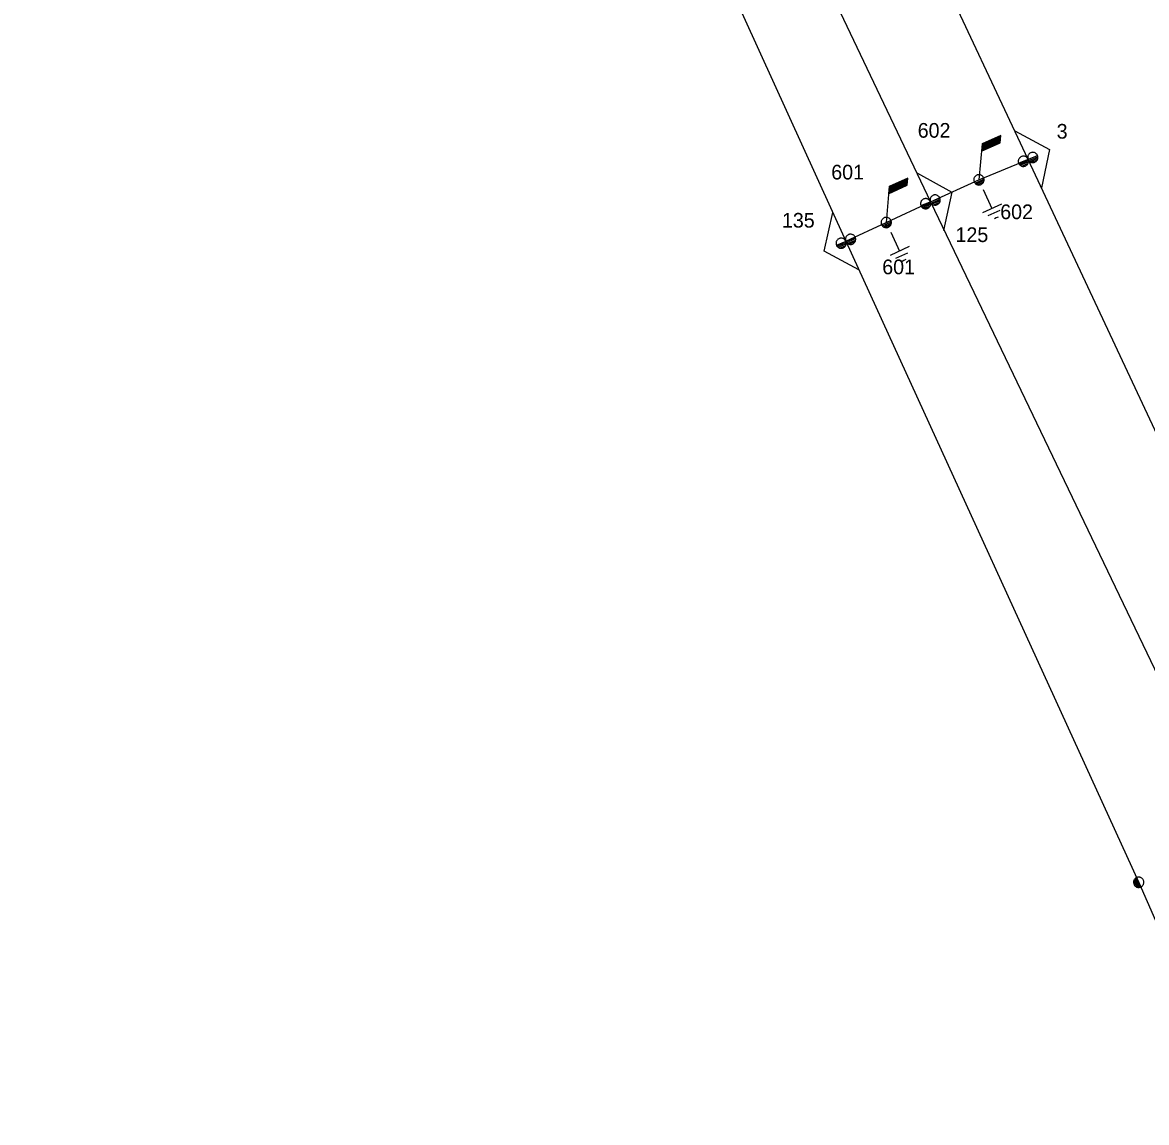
# Model space of a CAD drawing. Extents: x -536397 to -535454, y -1201642 to -1200953.
# Drawn here: x -536387.9 to -536253.8, y -1201275.2 to -1201144 of the extents above; entities that cross this region are included whole.
import ezdxf

# ---------------------------------------------------------------- set-up
doc = ezdxf.new("R2010")
doc.units = 0
for name, color, linetype in [('DOPLŇ_POPISY', 7, 'Continuous'), ('ELE_EON', 7, 'Continuous'), ('ELE_EON_POPIS', 7, 'Continuous'), ('Implicitní', 7, 'Continuous'), ('KN_HRAN_POHYBLIVÁ', 7, 'Continuous'), ('KONEC_VEDENÍ', 7, 'Continuous'), ('PLG_EXPORT_GPE', 7, 'Continuous'), ('PODZEM_NN_POPIS', 7, 'Continuous'), ('RÁMEČEK', 7, 'Continuous'), ('TECH_OCHR_PÁSMO_HRAN', 7, 'Continuous')]:
    doc.layers.add(name, color=color, linetype=linetype)

# ---------------------------------------------------------------- blocks, each defined once
blk = doc.blocks.new('VN860')
at = {"layer": 'RÁMEČEK'}
for points in [[(-3.74, 0), (0.01, 2.82)], [(0.01, 2.82), (3.76, 0)]]:
    blk.add_lwpolyline(points, dxfattribs=at)
blk = doc.blocks.new('VN440')
at = {"layer": 'ELE_EON_POPIS'}
for points in [[(1.22, 0), (1.21, 0.13), (1.19, 0.25), (1.16, 0.38), (1.11, 0.5), (1.05, 0.61), (0.98, 0.72), (0.9, 0.82), (0.81, 0.91), (0.71, 0.99), (0.6, 1.06), (0.49, 1.12), (0.37, 1.16), (0.25, 1.2), (0.12, 1.22), (-0.01, 1.22), (-0.14, 1.22), (-0.26, 1.2), (-0.39, 1.16), (-0.51, 1.12), (-0.62, 1.06), (-0.73, 0.99), (-0.83, 0.91), (-0.92, 0.82), (-1, 0.72), (-1.07, 0.61), (-1.13, 0.5), (-1.18, 0.38), (-1.21, 0.25), (-1.23, 0.13), (-1.24, 0), (-1.23, -0.13), (-1.21, -0.26), (-1.18, -0.38), (-1.13, -0.5), (-1.07, -0.62), (-1, -0.73), (-0.92, -0.83), (-0.83, -0.92), (-0.73, -1), (-0.62, -1.07), (-0.51, -1.13), (-0.39, -1.17), (-0.26, -1.2), (-0.14, -1.23), (-0.01, -1.23), (0.12, -1.23), (0.25, -1.2), (0.37, -1.17), (0.49, -1.13), (0.6, -1.07), (0.71, -1), (0.81, -0.92), (0.9, -0.83), (0.98, -0.73), (1.05, -0.62), (1.11, -0.5), (1.16, -0.38), (1.19, -0.26), (1.21, -0.13), (1.22, 0)], [(-1.24, 0), (1.22, 0)], [(-1.18, -0.34), (1.1, -0.34)], [(-1.01, -0.63), (0.97, -0.63)], [(-0.74, -0.92), (0.68, -0.92)]]:
    blk.add_lwpolyline(points, dxfattribs=at)
blk = doc.blocks.new('VN810')
at = {"layer": 'PLG_EXPORT_GPE'}
for points in [[(0, -1.25), (0, -3.75)], [(1.25, -3.75), (-1.25, -3.75)], [(0.77, -4.37), (-0.8, -4.37)], [(0, -5), (-0.25, -5)], [(0.27, -5), (0, -5)]]:
    blk.add_lwpolyline(points, dxfattribs=at)
blk = doc.blocks.new('VN450')
at = {"layer": 'ELE_EON_POPIS'}
for points in [[(0, 0), (-0.01, 0.13), (-0.03, 0.25), (-0.06, 0.38), (-0.11, 0.5), (-0.16, 0.61), (-0.23, 0.72), (-0.31, 0.82), (-0.4, 0.91), (-0.5, 0.99), (-0.61, 1.06), (-0.72, 1.11), (-0.84, 1.16), (-0.97, 1.19), (-1.09, 1.21), (-1.22, 1.22), (-1.35, 1.21), (-1.47, 1.19), (-1.59, 1.16), (-1.71, 1.11), (-1.83, 1.06), (-1.93, 0.99), (-2.03, 0.91), (-2.12, 0.82), (-2.2, 0.72), (-2.27, 0.61), (-2.33, 0.5), (-2.38, 0.38), (-2.41, 0.25), (-2.43, 0.13), (-2.44, 0), (-2.43, -0.13), (-2.41, -0.25), (-2.38, -0.38), (-2.33, -0.5), (-2.27, -0.61), (-2.2, -0.72), (-2.12, -0.82), (-2.03, -0.91), (-1.93, -0.99), (-1.83, -1.06), (-1.71, -1.11), (-1.59, -1.16), (-1.47, -1.19), (-1.35, -1.21), (-1.22, -1.22), (-1.09, -1.21), (-0.97, -1.19), (-0.84, -1.16), (-0.72, -1.11), (-0.61, -1.06), (-0.5, -0.99), (-0.4, -0.91), (-0.31, -0.82), (-0.23, -0.72), (-0.16, -0.61), (-0.11, -0.5), (-0.06, -0.38), (-0.03, -0.25), (-0.01, -0.13), (0, 0)], [(-2.44, 0), (2.44, 0)], [(2.44, 0), (2.43, 0.13), (2.41, 0.25), (2.38, 0.38), (2.33, 0.5), (2.27, 0.61), (2.2, 0.72), (2.12, 0.82), (2.03, 0.91), (1.94, 0.99), (1.83, 1.06), (1.71, 1.11), (1.6, 1.16), (1.47, 1.19), (1.35, 1.21), (1.22, 1.22), (1.09, 1.21), (0.97, 1.19), (0.84, 1.16), (0.72, 1.11), (0.61, 1.06), (0.5, 0.99), (0.4, 0.91), (0.31, 0.82), (0.23, 0.72), (0.16, 0.61), (0.11, 0.5), (0.06, 0.38), (0.03, 0.25), (0.01, 0.13), (0, 0), (0.01, -0.13), (0.03, -0.25), (0.06, -0.38), (0.11, -0.5), (0.16, -0.61), (0.23, -0.72), (0.31, -0.82), (0.4, -0.91), (0.5, -0.99), (0.61, -1.06), (0.72, -1.11), (0.84, -1.16), (0.97, -1.19), (1.09, -1.21), (1.22, -1.22), (1.35, -1.21), (1.47, -1.19), (1.6, -1.16), (1.71, -1.11), (1.83, -1.06), (1.94, -0.99), (2.03, -0.91), (2.12, -0.82), (2.2, -0.72), (2.27, -0.61), (2.33, -0.5), (2.38, -0.38), (2.41, -0.25), (2.43, -0.13), (2.44, 0)], [(-2.4, -0.31), (-0.04, -0.31)], [(-2.26, -0.61), (-0.17, -0.61)], [(-2.01, -0.92), (-0.42, -0.92)], [(0.04, -0.31), (2.4, -0.31)], [(0.17, -0.61), (2.27, -0.61)], [(0.42, -0.92), (2.02, -0.92)]]:
    blk.add_lwpolyline(points, dxfattribs=at)
blk = doc.blocks.new('VN001')
at = {"layer": 'Implicitní'}
for p, q in [((1.73, 3.03), (4.14, 3.03)), ((1.76, 3.08), (4.17, 3.08)), ((1.79, 3.13), (4.2, 3.13)), ((1.82, 3.18), (4.23, 3.18)), ((1.85, 3.23), (4.26, 3.23)), ((1.87, 3.28), (4.29, 3.28)), ((1.9, 3.33), (4.32, 3.33)), ((1.93, 3.38), (4.35, 3.38)), ((1.96, 3.43), (4.37, 3.43)), ((1.99, 3.48), (4.4, 3.48)), ((2.02, 3.53), (4.43, 3.53)), ((2.05, 3.58), (4.46, 3.58)), ((2.07, 3.63), (4.49, 3.63)), ((2.1, 3.68), (4.52, 3.68)), ((2.13, 3.73), (2.54, 3.73))]:
    blk.add_line(p, q, dxfattribs=at)
blk.add_lwpolyline([(2.13, 3.73), (0, 0)], dxfattribs=at)
blk.add_lwpolyline([(4.55, 3.73), (2.13, 3.73), (1.7, 2.98), (4.12, 2.99)], close=True, dxfattribs=at)

msp = doc.modelspace()

# ---------------------------------------------------------------- linework, layer by layer
at = {"layer": 'ELE_EON'}
for points in [[(-536387.85, -1200953.47), (-536384.37, -1200962.05), (-536350.06, -1201037.34), (-536318.97, -1201105.71), (-536289.66, -1201170.08)], [(-536346.44, -1200953.53), (-536361.66, -1200993.24), (-536320.28, -1201079.87), (-536279.58, -1201165.38)], [(-536267.93, -1201160.31), (-536301.44, -1201088.98), (-536346, -1200993.45), (-536331, -1200953.56)], [(-536219.44, -1201264.18), (-536230.28, -1201240.65), (-536267.93, -1201160.31)], [(-536279.58, -1201165.38), (-536243.47, -1201240.62), (-536227.12, -1201275.16)], [(-536289.66, -1201170.08), (-536254.73, -1201246.52), (-536245.05, -1201268.55)]]:
    msp.add_lwpolyline(points, dxfattribs=at)
at = {"layer": 'PODZEM_NN_POPIS'}
for points in [[(-536273.79, -1201162.75), (-536267.93, -1201160.31)], [(-536279.58, -1201165.38), (-536273.79, -1201162.75)], [(-536284.84, -1201167.84), (-536279.58, -1201165.38)], [(-536289.66, -1201170.08), (-536284.84, -1201167.84)]]:
    msp.add_lwpolyline(points, dxfattribs=at)

# ---------------------------------------------------------------- block references
at = {"layer": 'DOPLŇ_POPISY'}
for name, p, xscale, yscale, rotation in [('VN450', (-536267.93, -1201160.31), 0.5, 0.49999999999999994, 22.062133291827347), ('VN440', (-536273.79, -1201162.75), 0.5, 0.5, 24.430336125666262), ('VN450', (-536279.58, -1201165.38), 0.5000000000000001, 0.5, 21.177100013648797), ('VN440', (-536284.84, -1201167.84), 0.5, 0.5, 24.930505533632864), ('VN450', (-536289.66, -1201170.08), 0.5, 0.5, 22.397825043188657), ('VN440', (-536254.73, -1201246.52), 0.5, 0.5, -65.43590001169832)]:
    msp.add_blockref(name, p, dxfattribs=dict(at, xscale=xscale, yscale=yscale, rotation=rotation))
at = {"layer": 'KN_HRAN_POHYBLIVÁ'}
for p, rotation in [((-536267.93, -1201160.31), -64.87544721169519), ((-536279.58, -1201165.38), -65.51085832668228), ((-536289.66, -1201170.08), 114.56414439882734)]:
    msp.add_blockref('VN860', p, dxfattribs=dict(at, rotation=rotation))
at = {"layer": 'RÁMEČEK'}
for p, rotation in [((-536273.79, -1201162.75), 24.428316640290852), ((-536284.84, -1201167.84), 24.92261942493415)]:
    msp.add_blockref('VN810', p, dxfattribs=dict(at, rotation=rotation))
at = {"layer": 'TECH_OCHR_PÁSMO_HRAN'}
for p, rotation in [((-536273.79, -1201162.75), 24.430336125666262), ((-536284.84, -1201167.84), 24.930505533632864)]:
    msp.add_blockref('VN001', p, dxfattribs=dict(at, rotation=rotation))

# ---------------------------------------------------------------- texts
at = {"layer": 'KONEC_VEDENÍ'}
for s, p in [('602', (-536281.09, -1201157.73)), ('601', (-536291.4, -1201162.71))]:
    msp.add_text(s, height=1.75, dxfattribs=at).set_placement(p)
at = {"layer": 'PLG_EXPORT_GPE'}
for s, p in [('3', (-536264.52, -1201157.84)), ('602', (-536271.25, -1201167.44)), ('135', (-536297.28, -1201168.45)), ('125', (-536276.58, -1201170.17)), ('601', (-536285.32, -1201174.01))]:
    msp.add_text(s, height=1.75, dxfattribs=at).set_placement(p)

doc.saveas('drawing.dxf')
